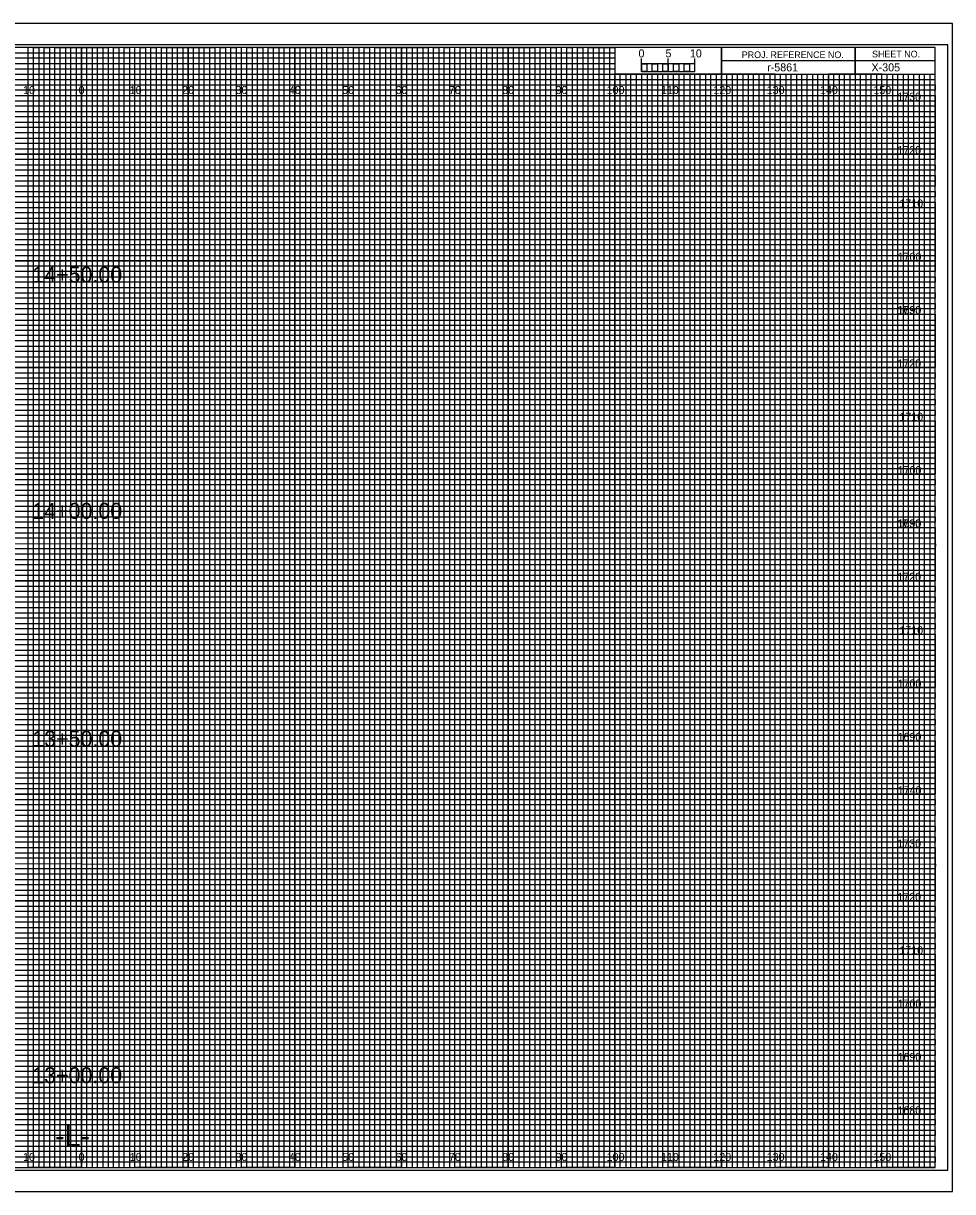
# Model space of a CAD drawing. Extents: x -15 to 323, y -5 to 6170.
# Drawn here: x 149.1 to 323.3, y 215.5 to 434.5 of the extents above; entities that cross this region are included whole.
import ezdxf

# ---------------------------------------------------------------- set-up
doc = ezdxf.new("R2010")
doc.units = 0
for name, color, linetype in [('Prop XS Alignment Label', 7, 'Continuous'), ('Prop XS Bar Scale Labels', 7, 'Continuous'), ('Prop XS DDE', 7, 'Continuous'), ('Prop XS DDE Earthwork Shape', 7, 'Continuous'), ('Prop XS DDE Slope Text', 7, 'Continuous'), ('Prop XS DDE Text', 7, 'Continuous'), ('Prop XS Earthwork Shape', 7, 'Continuous'), ('Prop XS Noise Wall', 7, 'Continuous'), ('Prop XS Project Number', 7, 'Continuous'), ('Prop XS Retaining Wall', 7, 'Continuous'), ('Prop XS Station Labels', 7, 'Continuous'), ('Prop XS Temporary Shoring', 7, 'Continuous'), ('Scratch_Level_3', 7, 'Continuous'), ('Scratch_Level_7', 7, 'Continuous'), ('Scratch_Level_8', 7, 'Continuous'), ('Sheet Cross Section Grid Minor 1 CELL', 7, 'Continuous')]:
    doc.layers.add(name, color=color, linetype=linetype)

msp = doc.modelspace()

# ---------------------------------------------------------------- linework, layer by layer
at = {"layer": 'Prop XS Alignment Label'}
for p, q in [((265, 425.49), (265, 427.9)), ((265, 426.9), (265, 427.9)), ((270, 425.49), (270, 427.9)), ((275, 425.49), (275, 427.9)), ((275, 426.9), (275, 427.9))]:
    msp.add_line(p, q, dxfattribs=at)
for points in [[(275, 426.9), (265, 426.9), (265, 425.49), (275, 425.49)], [(265, 426.9), (266, 426.9), (266, 425.49), (265, 425.49)], [(267, 426.9), (268, 426.9), (268, 425.49), (267, 425.49)], [(269, 426.9), (270, 426.9), (270, 425.49), (269, 425.49)], [(271, 426.9), (272, 426.9), (272, 425.49), (271, 425.49)], [(273, 426.9), (274, 426.9), (274, 425.49), (273, 425.49)]]:
    msp.add_lwpolyline(points, close=True, dxfattribs=at)
at = {"layer": 'Prop XS DDE'}
msp.add_lwpolyline([(-13.4, 215.5), (323.3, 215.5), (323.3, 434.5), (-13.4, 434.5)], close=True, dxfattribs=at)
at = {"layer": 'Prop XS DDE Slope Text'}
msp.add_lwpolyline([(-10.8, 219.5), (322.4, 219.5), (322.4, 430.5), (-10.8, 430.5)], close=True, dxfattribs=at)
at = {"layer": 'Prop XS DDE Text'}
for p, q in [((150, 220), (150, 430)), ((160, 220), (160, 430)), ((170, 220), (170, 430)), ((180, 220), (180, 430)), ((190, 220), (190, 430)), ((200, 220), (200, 430)), ((210, 220), (210, 430)), ((220, 220), (220, 430)), ((230, 220), (230, 430)), ((240, 220), (240, 430)), ((250, 220), (250, 430)), ((260, 220), (260, 424.69)), ((270, 220), (270, 424.69)), ((280, 220), (280, 424.69)), ((290, 220), (290, 424.69)), ((300, 220), (300, 424.69)), ((310, 220), (310, 424.69)), ((0, 420), (320, 420)), ((0, 410), (320, 410)), ((0, 400), (320, 400)), ((0, 390), (320, 390)), ((0, 380), (320, 380)), ((0, 370), (320, 370)), ((0, 360), (320, 360)), ((0, 350), (320, 350)), ((0, 340), (320, 340)), ((0, 330), (320, 330)), ((0, 320), (320, 320)), ((0, 310), (320, 310)), ((0, 300), (320, 300)), ((0, 290), (320, 290)), ((0, 280), (320, 280)), ((0, 270), (320, 270)), ((0, 260), (320, 260)), ((0, 250), (320, 250)), ((0, 240), (320, 240)), ((0, 230), (320, 230))]:
    msp.add_line(p, q, dxfattribs=at)
at = {"layer": 'Prop XS Earthwork Shape'}
for p, q in [((150, 430), (140, 430)), ((150, 220), (150, 430)), ((170, 430), (160, 430)), ((160, 430), (160, 220)), ((170, 220), (170, 430)), ((190, 430), (180, 430)), ((180, 430), (180, 220)), ((190, 220), (190, 430)), ((210, 430), (200, 430)), ((200, 430), (200, 220)), ((210, 220), (210, 430)), ((230, 430), (220, 430)), ((220, 430), (220, 220)), ((230, 220), (230, 430)), ((250, 430), (240, 430)), ((240, 430), (240, 220)), ((250, 220), (250, 430)), ((260, 430), (260, 220)), ((270, 220), (270, 425)), ((290, 425), (280, 425)), ((280, 425), (280, 220)), ((290, 220), (290, 425)), ((310, 425), (300, 425)), ((300, 425), (300, 220)), ((310, 220), (310, 425)), ((160, 220), (150, 220)), ((180, 220), (170, 220)), ((200, 220), (190, 220)), ((220, 220), (210, 220)), ((240, 220), (230, 220)), ((260, 220), (250, 220)), ((280, 220), (270, 220)), ((300, 220), (290, 220)), ((320, 220), (310, 220)), ((320, 220), (320, 220))]:
    msp.add_line(p, q, dxfattribs=at)
for points in [[(0, 420), (320, 420), (320, 410), (0, 410)], [(0, 400), (320, 400), (320, 390), (0, 390)], [(0, 380), (320, 380), (320, 370), (0, 370)], [(0, 360), (320, 360), (320, 350), (0, 350)], [(0, 340), (320, 340), (320, 330), (0, 330)], [(0, 320), (320, 320), (320, 310), (0, 310)], [(0, 300), (320, 300), (320, 290), (0, 290)], [(0, 280), (320, 280), (320, 270), (0, 270)], [(0, 260), (320, 260), (320, 250), (0, 250)], [(0, 240), (320, 240), (320, 230), (0, 230)]]:
    msp.add_lwpolyline(points, dxfattribs=at)
at = {"layer": 'Prop XS Noise Wall'}
for p, q in [((305, 430), (305, 425)), ((305, 425), (305, 430)), ((280, 427.5), (280, 425)), ((320, 427.49), (280, 427.49)), ((280, 425), (320, 425))]:
    msp.add_line(p, q, dxfattribs=at)
for points in [[(320, 430), (0, 430), (0, 220), (320, 220)], [(280, 430), (260, 430), (260, 425.03), (280, 425.03)], [(320, 430), (280, 430), (280, 425), (320, 425)]]:
    msp.add_lwpolyline(points, close=True, dxfattribs=at)
at = {"layer": 'Prop XS Retaining Wall'}
for p, q in [((267, 425), (266.01, 425)), ((266.01, 425), (266.01, 220)), ((267, 220), (267, 425)), ((269, 425), (268, 425)), ((268, 425), (268, 220)), ((269, 220), (269, 425)), ((266.01, 220), (265, 220)), ((268, 220), (267, 220))]:
    msp.add_line(p, q, dxfattribs=at)
for points in [[(150, 220), (151, 220), (151, 430), (152, 430), (152, 220)], [(152, 220), (153, 220), (153, 430), (154, 430), (154, 220)], [(155, 220), (156, 220), (156, 430), (157, 430), (157, 220)], [(157, 220), (158, 220), (158, 430), (159, 430), (159, 220)], [(160, 220), (161, 220), (161, 430), (162, 430), (162, 220)], [(162, 220), (163, 220), (163, 430), (164, 430), (164, 220)], [(165, 220), (166, 220), (166, 430), (167, 430), (167, 220)], [(167, 220), (168, 220), (168, 430), (169, 430), (169, 220)], [(170, 220), (171, 220), (171, 430), (172, 430), (172, 220)], [(172, 220), (173, 220), (173, 430), (174, 430), (174, 220)], [(175, 220), (176, 220), (176, 430), (177, 430), (177, 220)], [(177, 220), (178, 220), (178, 430), (179, 430), (179, 220)], [(180, 220), (181, 220), (181, 430), (182, 430), (182, 220)], [(182, 220), (183, 220), (183, 430), (184, 430), (184, 220)], [(185, 220), (186, 220), (186, 430), (187, 430), (187, 220)], [(187, 220), (188, 220), (188, 430), (189, 430), (189, 220)], [(190, 220), (191, 220), (191, 430), (192, 430), (192, 220)], [(192, 220), (193, 220), (193, 430), (194, 430), (194, 220)], [(195, 220), (196, 220), (196, 430), (197, 430), (197, 220)], [(197, 220), (198, 220), (198, 430), (199, 430), (199, 220)], [(200, 220), (201, 220), (201, 430), (202, 430), (202, 220)], [(202, 220), (203, 220), (203, 430), (204, 430), (204, 220)], [(205, 220), (206, 220), (206, 430), (207, 430), (207, 220)], [(207, 220), (208, 220), (208, 430), (209, 430), (209, 220)], [(210, 220), (211, 220), (211, 430), (212, 430), (212, 220)], [(212, 220), (213, 220), (213, 430), (214, 430), (214, 220)], [(215, 220), (216, 220), (216, 430), (217, 430), (217, 220)], [(217, 220), (218, 220), (218, 430), (219, 430), (219, 220)], [(220, 220), (221, 220), (221, 430), (222, 430), (222, 220)], [(222, 220), (223, 220), (223, 430), (224, 430), (224, 220)], [(225, 220), (226, 220), (226, 430), (227, 430), (227, 220)], [(227, 220), (228, 220), (228, 430), (229, 430), (229, 220)], [(230, 220), (231, 220), (231, 430), (232, 430), (232, 220)], [(232, 220), (233, 220), (233, 430), (234, 430), (234, 220)], [(235, 220), (236, 220), (236, 430), (237, 430), (237, 220)], [(237, 220), (238, 220), (238, 430), (239, 430), (239, 220)], [(240, 220), (241, 220), (241, 430), (242, 430), (242, 220)], [(242, 220), (243, 220), (243, 430), (244, 430), (244, 220)], [(245, 220), (246, 220), (246, 430), (247, 430), (247, 220)], [(247, 220), (248, 220), (248, 430), (249, 430), (249, 220)], [(250, 220), (251, 220), (251, 430), (252, 430), (252, 220)], [(252, 220), (253, 220), (253, 430), (254, 430), (254, 220)], [(255, 220), (256, 220), (256, 430), (257, 430), (257, 220)], [(257, 220), (258, 220), (258, 430), (259, 430), (259, 220)], [(260, 220), (261, 220), (261, 425), (262.02, 425), (262.02, 220)], [(262, 220), (263, 220), (263, 425), (263.99, 425), (263.99, 220)], [(270, 220), (270.98, 220), (270.98, 425), (272, 425), (272, 220)], [(272, 220), (273, 220), (273, 425), (274.05, 425), (274.05, 220)], [(275, 220), (276, 220), (276, 425), (277, 425), (277, 220)], [(277, 220), (278, 220), (278, 425), (279, 425), (279, 220)], [(280, 220), (281, 220), (281, 425), (282, 425), (282, 220)], [(282, 220), (283, 220), (283, 425), (284, 425), (284, 220)], [(285, 220), (286, 220), (286, 425), (287, 425), (287, 220)], [(287, 220), (288, 220), (288, 425), (289, 425), (289, 220)], [(290, 220), (291, 220), (291, 425), (292, 425), (292, 220)], [(292, 220), (293, 220), (293, 425), (294, 425), (294, 220)], [(295, 220), (296, 220), (296, 425), (297, 425), (297, 220)], [(297, 220), (298, 220), (298, 425), (299, 425), (299, 220)], [(300, 220), (301, 220), (301, 425), (302, 425), (302, 220)], [(302, 220), (303, 220), (303, 425), (304, 425), (304, 220)], [(305, 220), (306, 220), (306, 425), (307, 425), (307, 220)], [(307, 220), (308, 220), (308, 425), (309, 425), (309, 220)], [(310, 220), (311, 220), (311, 425), (312, 425), (312, 220)], [(312, 220), (313, 220), (313, 425), (314, 425), (314, 220)], [(315, 220), (316, 220), (316, 425), (317, 425), (317, 220)], [(317, 220), (318, 220), (318, 425), (319, 425), (319, 220)]]:
    msp.add_lwpolyline(points, dxfattribs=at)
at = {"layer": 'Prop XS Station Labels'}
for points in [[(145, 220), (155, 220), (155, 430), (165, 430), (165, 220), (175, 220), (175, 430), (185, 430), (185, 220), (195, 220), (195, 430), (205, 430), (205, 220), (215, 220), (215, 430), (225, 430), (225, 220), (235, 220), (235, 430), (245, 430), (245, 220), (255, 220), (255, 430), (259.93, 430), (260, 430), (260, 425), (264.99, 425), (264.99, 220), (275, 220), (275, 425), (285, 425), (285, 220), (295, 220), (295, 425), (305, 425), (305, 220), (315, 220), (315, 425)], [(0, 425), (275, 425)], [(0, 405), (320, 405), (320, 415), (0, 415)], [(0, 385), (320, 385), (320, 395), (0, 395)], [(0, 365), (320, 365), (320, 375), (0, 375)], [(0, 345), (320, 345), (320, 355), (0, 355)], [(0, 325), (320, 325), (320, 335), (0, 335)], [(0, 305), (320, 305), (320, 315), (0, 315)], [(0, 285), (320, 285), (320, 295), (0, 295)], [(0, 265), (320, 265), (320, 275), (0, 275)], [(0, 245), (320, 245), (320, 255), (0, 255)], [(0, 225), (320, 225), (320, 235), (0, 235)]]:
    msp.add_lwpolyline(points, dxfattribs=at)
at = {"layer": 'Scratch_Level_7'}
for p, q in [((323.3, 434.5), (-13.4, 434.5)), ((-13.4, 215.5), (323.3, 215.5))]:
    msp.add_line(p, q, dxfattribs=at)
at = {"layer": 'Sheet Cross Section Grid Minor 1 CELL'}
for p, q in [((0, 429), (260, 429)), ((260, 427.98), (0, 427.98)), ((260, 429), (260, 427.98)), ((0, 427), (260, 427)), ((260, 425.89), (0, 425.89)), ((260, 427), (260, 425.89)), ((0, 424), (320, 424))]:
    msp.add_line(p, q, dxfattribs=at)
for points in [[(0, 423), (270, 423), (320, 423), (320, 422), (0, 422)], [(0, 421), (320, 421), (320, 419), (0, 419)], [(0, 418), (320, 418), (320, 417), (0, 416.98)], [(0, 416), (320, 416), (320, 414), (0, 414)], [(0, 413), (320, 413), (320, 412), (0, 412)], [(0, 411), (320, 411), (320, 409), (0, 409)], [(0, 408), (320, 408), (320, 407), (0, 407)], [(0, 406), (320, 406), (320, 404), (0, 404)], [(0, 403), (320, 403), (320, 402), (0, 402)], [(0, 401), (320, 401), (320, 399), (0, 399)], [(0, 398), (320, 398), (320, 397), (0, 397)], [(0, 396), (320, 396), (320, 393.95), (320, 393), (320, 392), (0, 392)], [(0, 394), (320, 394), (320, 393), (0, 393)], [(0, 391), (320, 391), (320, 389), (0, 389.03)], [(0, 389.03), (320, 389), (320, 388), (0, 388)], [(0, 387), (320, 387), (320, 386), (0, 386)], [(0, 384), (320, 384), (320, 383), (0, 383)], [(0, 382), (320, 382), (320, 381), (0, 381)], [(-0.07, 378.89), (320, 378.89), (320, 377.88), (-0.07, 377.88)], [(0, 377), (320, 377), (320, 376), (0, 376)], [(0, 374), (320, 374), (320, 373), (0, 373)], [(0, 372), (320, 372), (320, 371), (0, 371)], [(0, 369), (320, 369), (320, 368), (0, 368)], [(0, 367), (320, 367), (320, 366), (0, 366)], [(0, 364), (320, 364), (320, 363), (0, 363)], [(0, 362), (320, 362), (320, 361), (0, 361)], [(0, 359), (320, 359), (319.99, 357.98), (0, 358)], [(0, 357), (320, 357), (320, 356), (0, 356)], [(0, 354), (320, 354), (320, 353), (0, 353)], [(0, 352), (320, 352), (320, 351), (0, 351)], [(0, 349), (320, 349), (320, 348), (0, 348)], [(0, 347), (320, 347), (320, 346), (0, 346)], [(0, 344), (320, 344), (320, 343), (0, 343)], [(0, 342), (320, 342), (320, 341), (0, 341)], [(0, 339), (320, 339), (320, 338), (0, 338)], [(0, 336.99), (320.07, 336.91), (320, 336), (0, 336)], [(0, 334), (320, 334), (320, 333), (0, 333)], [(0, 332), (320, 332), (320, 331), (0, 331)], [(0, 329), (320, 329), (320, 328), (0, 328)], [(0, 327), (320, 327), (320, 326), (0, 326)], [(0, 324), (320, 324), (320, 323), (0, 323)], [(0, 322), (320, 322), (320, 321), (0, 321)], [(0, 319), (320, 319), (320, 318), (0, 318)], [(0, 317), (320, 317), (320, 316), (0, 316)], [(0, 314), (320, 314), (320, 313), (0, 313)], [(0, 312), (320, 312), (320, 311), (0, 311)], [(0, 309), (320, 309), (320, 308), (0, 308)], [(0, 307), (320, 307), (320, 306), (0, 306)], [(0, 304), (320, 304), (320, 303), (0, 303)], [(0, 302), (320, 302), (320, 301), (0, 301)], [(0, 299), (320, 299), (319.99, 297.98), (0, 298)], [(0, 297), (320, 297), (320, 296), (0, 296)], [(0, 294), (320, 294), (320, 293), (0, 293)], [(0, 292), (320, 292), (320, 291), (0, 291)], [(0, 289), (320, 289), (320, 288), (0, 288)], [(0, 287), (320, 287), (320, 286), (0, 286)], [(0, 284), (320, 284), (320, 283), (0, 283)], [(0, 282), (320, 282), (320, 281), (0, 281)], [(0, 279), (320, 279), (320, 278), (0, 278)], [(0, 276.99), (320.07, 276.91), (320, 276), (0, 276)], [(0, 274), (320, 274), (320, 273), (0, 273)], [(0, 272), (320, 272), (320, 271), (0, 271)], [(0, 269), (320, 269), (320, 268), (0, 268)], [(0, 267), (320, 267), (320, 266), (0, 266)], [(0, 264), (320, 264), (320, 263), (0, 263)], [(0, 262), (320, 262), (320, 261), (0, 261)], [(0, 259), (320, 259), (320, 258), (0, 258)], [(0, 257), (320, 257), (320, 256), (0, 256)], [(0, 254), (320, 254), (320, 253), (0, 253)], [(0, 252), (320, 252), (320, 251), (0, 251)], [(0, 249), (320, 249), (320, 248), (0, 248)], [(0, 247), (320, 247), (320, 246), (0, 246)], [(0, 244), (320, 244), (320, 243), (0, 243)], [(0, 242), (320, 242), (320, 241), (0, 241)], [(0, 239), (320, 239), (320, 238), (0, 238)], [(0, 237), (320, 237), (320, 236), (0, 236)], [(0, 234), (320, 234), (320, 233), (0, 233)], [(0, 232), (320, 232), (320, 231), (0, 231)], [(0, 229), (320, 229), (320, 228), (0, 228)], [(0, 227), (320, 227), (320, 226), (0, 226)], [(0, 224), (320, 224), (320, 223), (0, 223)], [(0, 222), (320, 222), (320, 221), (0, 221)]]:
    msp.add_lwpolyline(points, dxfattribs=at)

# ---------------------------------------------------------------- texts
at = {"layer": 'Prop XS Alignment Label'}
for s, height, p in [('0', 1.5, (264.41, 428.12)), ('-L-', 4, (155.06, 224))]:
    msp.add_text(s, height=height, dxfattribs=at).set_placement(p)
at = {"layer": 'Prop XS Bar Scale Labels'}
for s, p in [('5', (269.47, 428.12)), ('10', (274.04, 428.12))]:
    msp.add_text(s, height=1.5, dxfattribs=at).set_placement(p)
at = {"layer": 'Prop XS DDE Earthwork Shape'}
msp.add_text('X-305', height=1.5, dxfattribs=at).set_placement((308.09, 425.5))
at = {"layer": 'Prop XS Noise Wall'}
for s, p in [('PROJ. REFERENCE NO.', (283.77, 427.99)), ('SHEET NO.', (308.19, 428.12))]:
    msp.add_text(s, height=1.25, dxfattribs=at).set_placement(p)
at = {"layer": 'Prop XS Project Number'}
msp.add_text('r-5861', height=1.5, dxfattribs=at).set_placement((288.53, 425.5))
at = {"layer": 'Prop XS Temporary Shoring'}
for s, p in [('14+50.00', (150.77, 385.9)), ('14+00.00', (150.77, 341.62)), ('13+50.00', (150.77, 298.9)), ('13+00.00', (150.77, 235.82))]:
    msp.add_text(s, height=3, dxfattribs=at).set_placement(p)
at = {"layer": 'Scratch_Level_3'}
for s, p in [('1730', (312.92, 420)), ('1720', (312.93, 410)), ('1710', (313.31, 400)), ('1700', (312.98, 390)), ('1730', (312.92, 380)), ('1690', (312.97, 380)), ('1720', (312.93, 370)), ('1710', (313.31, 360)), ('1700', (312.98, 350)), ('1730', (312.92, 340)), ('1690', (312.97, 340)), ('1720', (312.93, 330)), ('1710', (313.31, 320)), ('1700', (312.98, 310)), ('1690', (312.97, 300)), ('1740', (313, 290)), ('1730', (312.92, 280)), ('1720', (312.93, 270)), ('1710', (313.31, 260)), ('1700', (312.98, 250)), ('1690', (312.97, 240)), ('1680', (312.95, 230))]:
    msp.add_text(s, height=1.5, dxfattribs=at).set_placement(p)
at = {"layer": 'Scratch_Level_8'}
for s, p in [('10', (149.04, 421.25)), ('0', (159.45, 421.25)), ('0', (159.45, 421.25)), ('10', (169.04, 421.25)), ('20', (178.86, 421.25)), ('30', (188.86, 421.25)), ('40', (198.86, 421.25)), ('50', (208.86, 421.25)), ('60', (218.86, 421.25)), ('70', (228.86, 421.25)), ('80', (238.86, 421.25)), ('90', (248.86, 421.25)), ('100', (258.44, 421.25)), ('110', (268.62, 421.25)), ('120', (278.44, 421.25)), ('130', (288.44, 421.25)), ('140', (298.44, 421.25)), ('150', (308.44, 421.25)), ('10', (149.04, 221.25)), ('0', (159.45, 221.25)), ('0', (159.45, 221.25)), ('10', (169.04, 221.25)), ('20', (178.86, 221.25)), ('30', (188.86, 221.25)), ('40', (198.86, 221.25)), ('50', (208.86, 221.25)), ('60', (218.86, 221.25)), ('70', (228.86, 221.25)), ('80', (238.86, 221.25)), ('90', (248.86, 221.25)), ('100', (258.44, 221.25)), ('110', (268.62, 221.25)), ('120', (278.44, 221.25)), ('130', (288.44, 221.25)), ('140', (298.44, 221.25)), ('150', (308.44, 221.25))]:
    msp.add_text(s, height=1.5, dxfattribs=at).set_placement(p)

doc.saveas('drawing.dxf')
